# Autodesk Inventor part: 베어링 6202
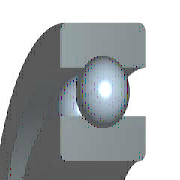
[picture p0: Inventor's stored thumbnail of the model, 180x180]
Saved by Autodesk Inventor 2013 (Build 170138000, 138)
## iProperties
Created: 2015-12
Part Number: 베어링 6202
Material: 강철, 연강
Description: 깊은 그루브 볼 베어링
Document SubType Name: Modeling
Standard: KS B 2023
Designer: mdu
Standards Organization: KS
Language: ko-KR
Size Designation: 6202 - 15 x 35 x 11
Categories: <MemberInstance><Categories><Category DisplayName="샤프트 부품" InternalName="7f7aeb1f-a693-4053-b835-cee3144e0d98" Mnemonic="SHFT"><Category DisplayName="베어링" Inter
Density: 7.86 g/cm^3
Mass: 45.8724 g
Surface Area: 51.5584 cm^2
Volume: 5.83618 cm^3
Company: 한국ATC센터
IsCustomPart: 1
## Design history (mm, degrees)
sketch "스케치" dims "d0" = 5.2 (= -0.26 x WD + 0.26 x BD)
  geometry: L1 (2.9, 12.5)-(8.1, 12.5); L2 (5.5, 12.5)-(5.5, 9.9); L3 (5.5, 12.5)-(5.5, 15.1); L4 (3.568, 10.76)-(0, 10.76); L5 (0, 7.5)-(11, 7.5); L6 (3.568, 14.24)-(0, 14.24); L7 (0, 17.5)-(11, 17.5); L8 (11, 7.5)-(11, 10.76); L9 (7.432, 10.76)-(11, 10.76); L10 (7.432, 14.24)-(11, 14.24); L11 (11, 17.5)-(11, 14.24); L12 (-1.4, 0)-(8.4, 0) reference; L13 (0, -0.3)-(0, 5.3) reference
  constraints: 22 end point, 4 point on line, 2 collinear, 2 perpendicular, 2 symmetric about line, 1 midpoint, 1 parallel, 14 other
  dimensions: "d9" = 15 diameter of L5 L12 (= WD); "d11" = 35 diameter of L7 L12 (= BD); "d12" = 11 distance between parallel lines of L8 L13 (= KB); "d13" = 21.52 diameter of L9 L12 (= 0.326 x BD + 0.674 x WD)
revolve "본체" stored, may be unused: angle "d6" = 90 deg
revolve "볼" stored, may be unused: angle "d7" = 90 deg
pattern_circular "IDS_ARRAYBALL[SIMPL:T]" dims angle "d3" = 360 deg
body "Solid1"
fillet "모깎기1" dims "d1" = 0.6 (= KRS)
other parameters: "WD" = 15 [user parameter; used in 5 equation terms], "BD" = 35 [user parameter; used in 5 equation terms], "KB" = 11 [user parameter; used in 1 equation term], "KRS" = 0.6 [user parameter; used in 1 equation term], "d4" = 0, "d5" = 0, "d8" = 0, "d14" = 0, "d15" = 0, "BBA" = 0 [user parameter], "BC0" = 3750000 [user parameter], "BC" = 7800000 [user parameter], "BR" = 17.5 (= 0.5 x BD) [user parameter], "WR" = 7.5 (= 0.5 x WD) [user parameter]
